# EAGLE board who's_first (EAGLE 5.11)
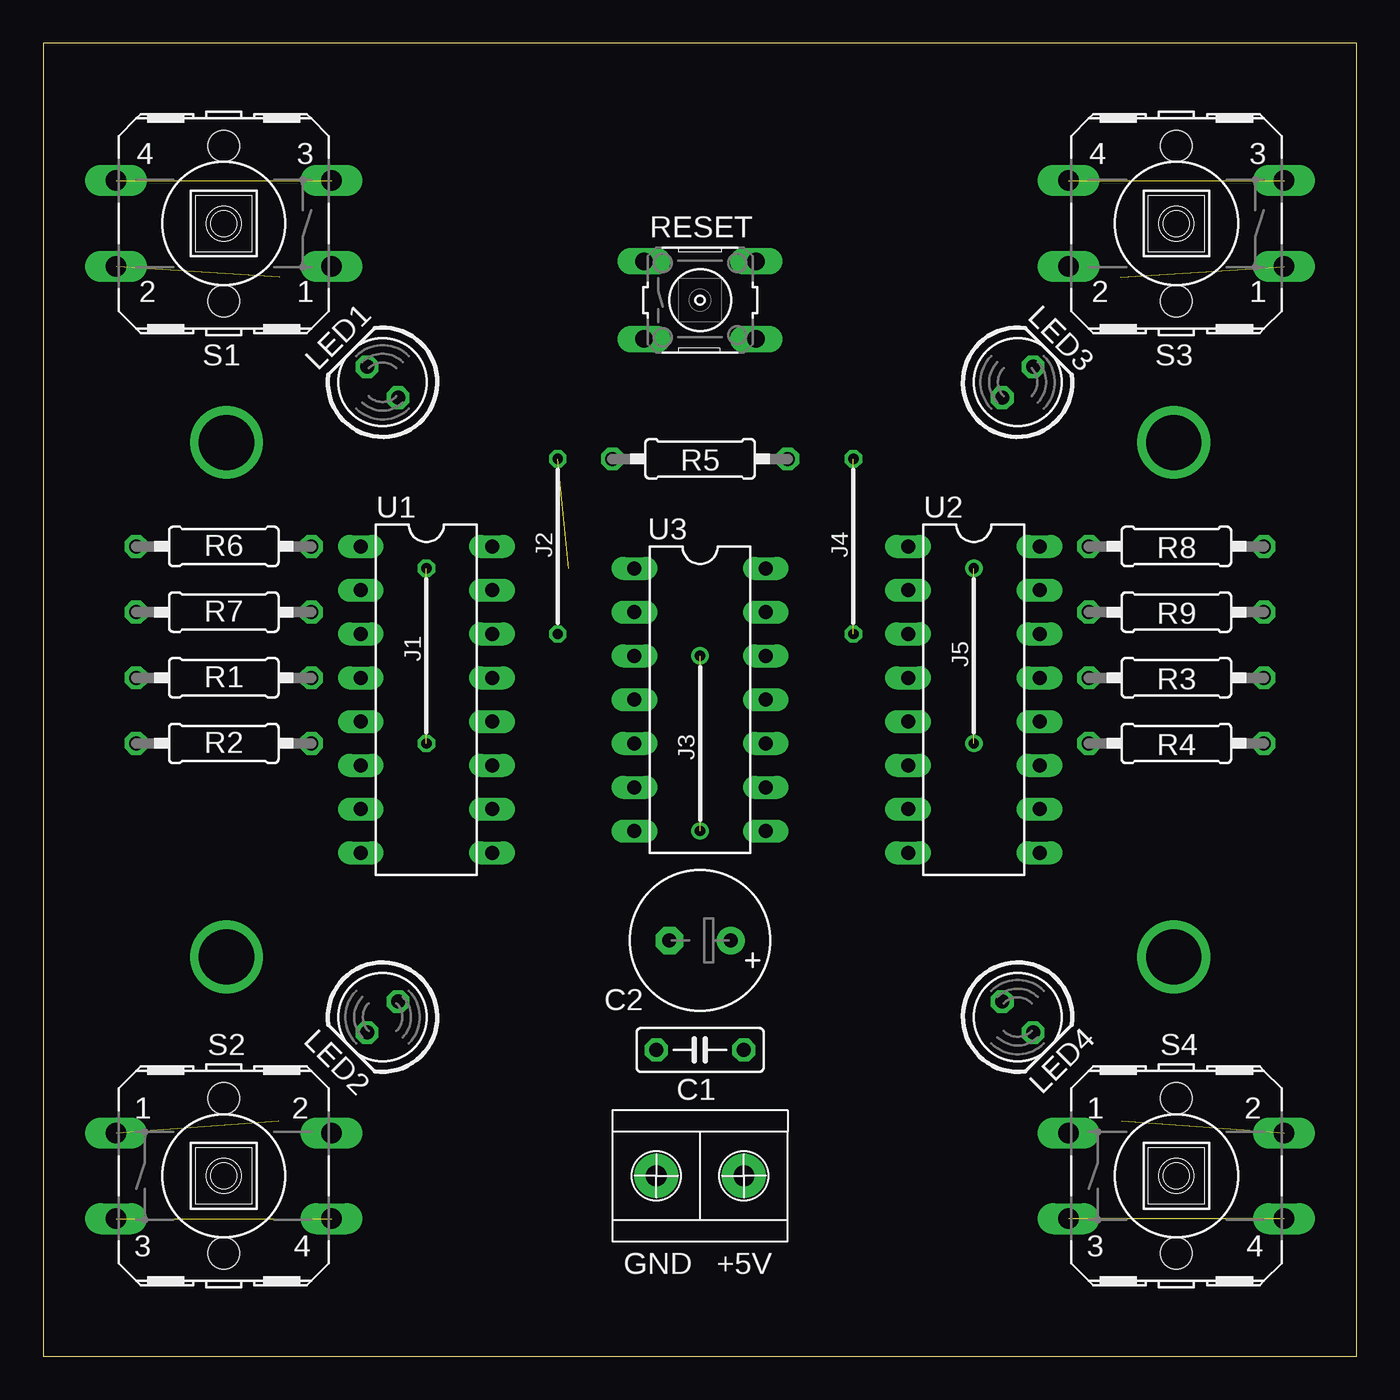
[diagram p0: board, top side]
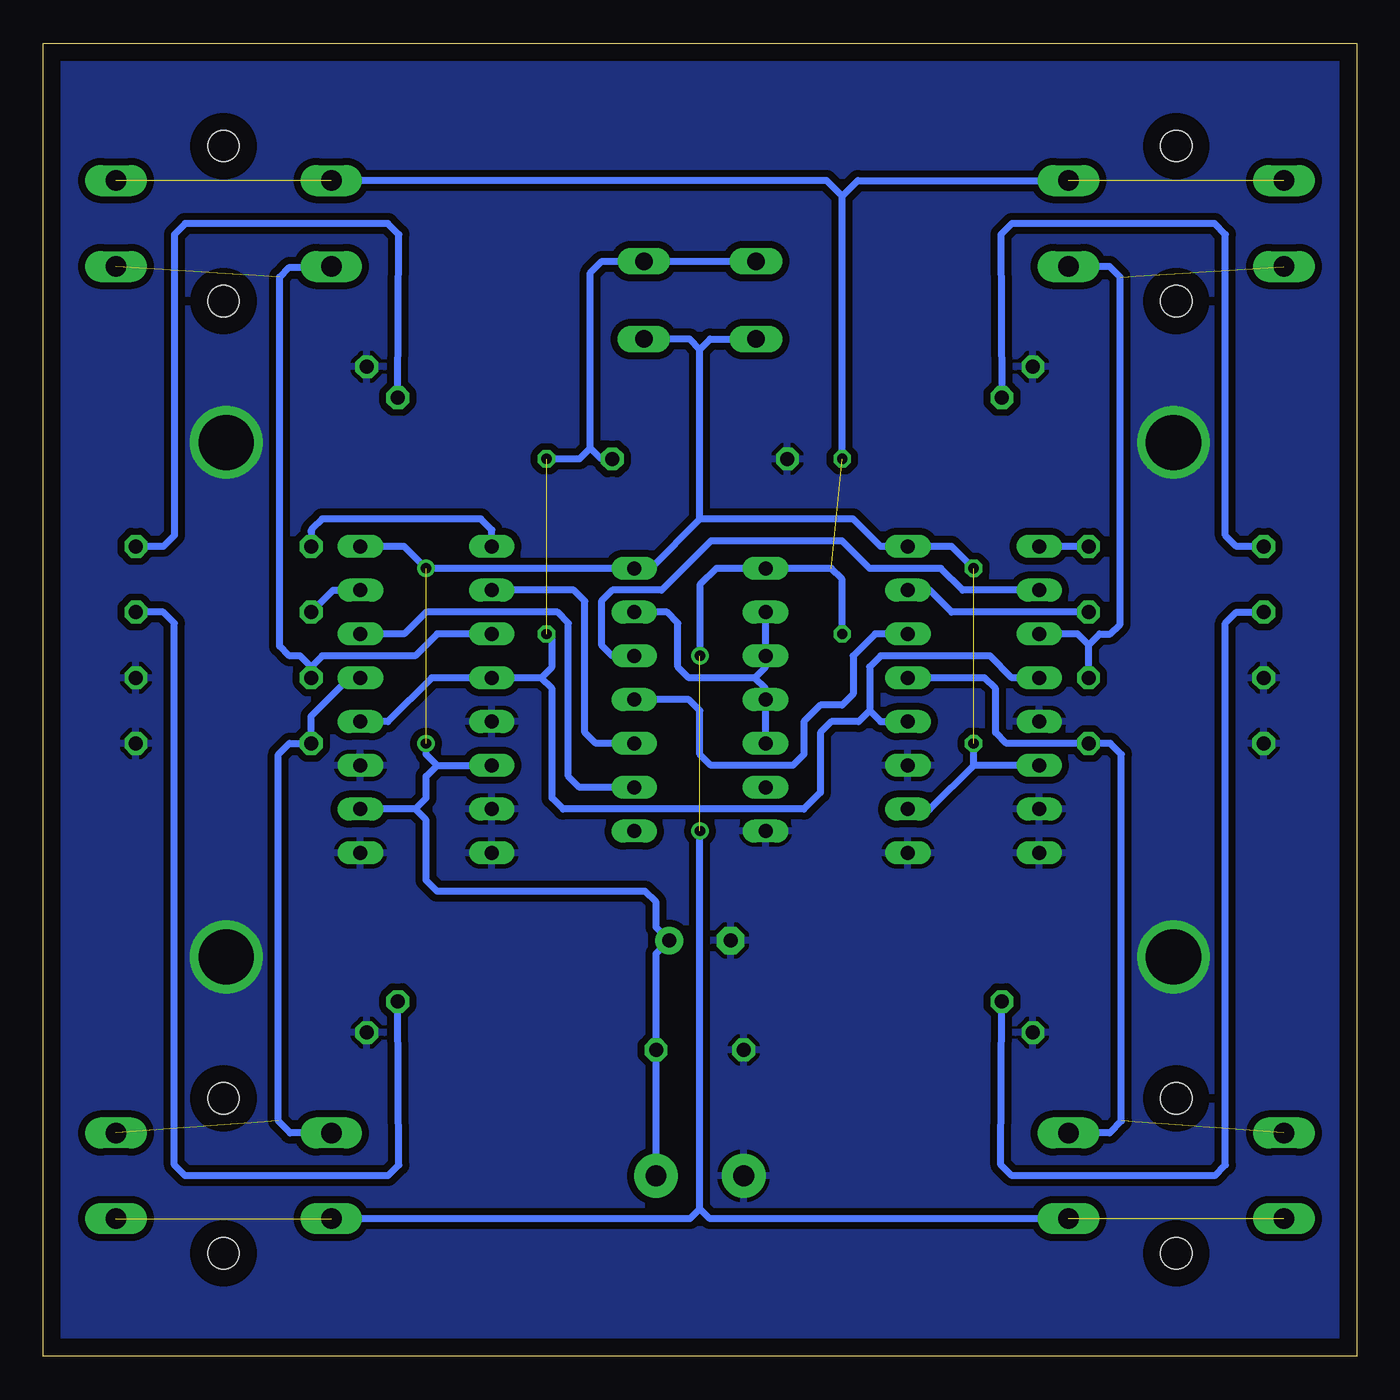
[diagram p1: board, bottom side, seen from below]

Size 76.19 x 76.19 mm. Coordinates in mm from the lower left corner, seen from the top.
Outline: 0,0 76.19,0 76.19,76.19 0,76.19 0,0
Copper layers (1*16): Top 0.035mm / dielectric 1.5mm / Bottom 0.035mm
Design rules "default": minimum track width 10mil, minimum drill 24mil, track to track 8mil, track to pad 8mil, pad to pad 8mil, via to via 8mil, smd to smd 8mil, copper to edge 40mil, drill to drill 8mil, minimum pad ring 10mil, minimum via ring 8mil, stop-mask expansion 4mil, vias tented up to drill 0mil, thermal gap 10mil

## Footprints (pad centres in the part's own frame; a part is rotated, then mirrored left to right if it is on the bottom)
C050-025X075 = drill 0.813 octagon: 1 -2.54,0; 2 2.54,0
E3,5-8 = drill 0.813 pad 1.6 round: + -1.778,0 | drill 0.813 pad 1.6 octagon: - 1.778,0
LED5MM = drill 0.813 octagon: A -1.27,0; K 1.27,0
0207/10 = drill 0.813 octagon: 1 -5.08,0; 2 5.08,0
B3F-10XX = drill 1.016 long: 1 -3.251,2.261; 2 3.251,2.261; 3 -3.251,-2.261; 4 3.251,-2.261
B3F-40XX = drill 1.194 long: 1 -6.248,2.489; 2 6.248,2.489; 3 -6.248,-2.489; 4 6.248,-2.489 | hole 1.803: 0,-4.496; 0,4.496
DIL16 = drill 0.813 long: 1 -8.89,-3.81; 2 -6.35,-3.81; 3 -3.81,-3.81; 4 -1.27,-3.81; 5 1.27,-3.81; 6 3.81,-3.81; 7 6.35,-3.81; 8 8.89,-3.81; 9 8.89,3.81; 10 6.35,3.81; 11 3.81,3.81; 12 1.27,3.81; 13 -1.27,3.81; 14 -3.81,3.81; 15 -6.35,3.81; 16 -8.89,3.81
DIL14 = drill 0.813 long: 1 -7.62,-3.81; 2 -5.08,-3.81; 3 -2.54,-3.81; 4 0,-3.81; 5 2.54,-3.81; 6 5.08,-3.81; 7 7.62,-3.81; 8 7.62,3.81; 9 5.08,3.81; 10 2.54,3.81; 11 0,3.81; 12 -2.54,3.81; 13 -5.08,3.81; 14 -7.62,3.81
ARK2 = drill 1.2 pad 2.54 round: 1 -2.54,0; 3 2.54,0 | drill 0.8 pad 2.54 round: 2 2.54,0

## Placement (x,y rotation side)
C1  100n  [C050-025X075]  38.1,17.78 180 top
C2  100u  [E3,5-8]  38.1,24.13 180 top
LED1  [LED5MM]  19.68,56.51 135 top
LED2  [LED5MM]  19.68,19.68 225 top
LED3  [LED5MM]  56.52,56.51 45 top
LED4  [LED5MM]  56.52,19.68 315 top
R1  100k  [0207/10]  10.48,39.37 180 top
R2  100k  [0207/10]  10.48,35.56 180 top
R3  100k  [0207/10]  65.72,39.37 0 top
R4  100k  [0207/10]  65.72,35.56 0 top
R5  100k  [0207/10]  38.1,52.07 0 top
R6  300  [0207/10]  10.48,46.99 180 top
R7  300  [0207/10]  10.48,43.18 180 top
R8  300  [0207/10]  65.72,46.99 0 top
R9  300  [0207/10]  65.72,43.18 0 top
RESET  [B3F-10XX]  38.1,61.28 0 top
S1  [B3F-40XX]  10.48,65.72 180 top
S2  [B3F-40XX]  10.48,10.48 0 top
S3  [B3F-40XX]  65.72,65.72 180 top
S4  [B3F-40XX]  65.72,10.48 0 top
U1  4027  [DIL16]  22.23,38.1 270 top
U2  4027  [DIL16]  53.97,38.1 270 top
U3  4012  [DIL14]  38.1,38.1 270 top
U$1  ARK2  [ARK2]  38.1,10.48 0 top

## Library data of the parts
C1 C2 R1-R9 = rcl
LED1-LED4 = led
RESET = switch-omron; MPN: B3F-1000; OC_FARNELL: 176432; OC_NEWARK: 36M3542
S1-S4 = switch-omron; MF: OMRON COMPONENTS USA; MPN: B3F-4000; OC_FARNELL: 176434; OC_NEWARK: 36K3105
U1-U3 = 40xx
U$1 = ark2

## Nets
GND: C1.2 C2.- LED1.K LED2.K LED3.K LED4.K R1.2 R2.2 R3.2 R4.2 R5.1 U1.5 U1.7 U1.8 U1.9 U1.11 U2.5 U2.7 U2.8 U2.9 U2.11 U3.7 U$1.1
N$1: R6.1 U1.1
N$2: R5.2 RESET.1 RESET.2 U1.4 U1.12 U2.4 U2.12
N$3: U1.2 U3.12
N$4: U1.14 U3.11
N$5: U2.2 U3.10
N$6: U2.14 U3.9
N$7: U3.2 U3.3 U3.4 U3.5 U3.13
N$8: C1.1 C2.+ RESET.3 RESET.4 U1.6 U1.10 U1.16 U2.6 U2.10 U2.16 U3.14 U$1.2
N$9: R7.1 U1.15
N$11: S1.3 S1.4 S2.3 S2.4 S3.3 S3.4 S4.3 S4.4 U3.1
N$12: R1.1 S1.1 S1.2 U1.3
N$13: R2.1 S2.1 S2.2 U1.13
N$14: R3.1 S3.1 S3.2 U2.3
N$15: R4.1 S4.1 S4.2 U2.13
N$16: R8.1 U2.1
N$17: R9.1 U2.15
N$18: LED1.A R6.2
N$19: LED2.A R7.2
N$20: LED3.A R8.2
N$21: LED4.A R9.2

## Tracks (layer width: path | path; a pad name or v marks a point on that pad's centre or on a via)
GND  (via drill 3.2)
  other vias: 10.64,53.02 65.56,53.02 10.64,23.18 65.56,23.18
  pour Bottom (isolate 0.406): -0.32,76.52 76.52,76.52 76.52,-0.32 -0.32,-0.32
N$1
  Bottom 0.406: R6.1 U1.1
N$2  (via drill 0.6)  (1 unrouted)
  Bottom 0.406: U2.12 56.2,36.83 53.66,39.37 U2.4 47.31,39.37 | 47.31,39.37 46.67,38.73 46.67,32.38 46.04,31.75 32.07,31.75 31.11,32.7 31.11,36.2 30.48,36.83 28.89,36.83 28.26,37.46 | U1.4 20,39.37 21.27,40.64 27.62,40.64 28.26,40 28.26,37.46 | RESET.1 RESET.2 43.78,63.54 44.45,62.87 44.45,52.7 | 44.45,52.7 43.82,52.07 R5.2 | 47.31,39.37 46.67,40 46.67,41.59 v46.99,41.91 | U1.12 27.62,36.83 28.26,37.46 | v46.99,52.07 45.08,52.07 44.45,52.7
N$3
  Bottom 0.406: U1.2 22.86,44.45 24.13,45.72 28.26,45.72 29.85,47.31 37.46,47.31 40.32,44.45 43.18,44.45 43.82,43.81 43.82,41.27 43.18,40.64 U3.12
N$4
  Bottom 0.406: U3.11 38.74,38.1 38.1,37.46 38.1,34.92 37.46,34.29 32.7,34.29 32.07,34.92 32.07,36.83 31.11,37.78 29.85,37.78 29.21,38.42 29.21,40.64 27.94,41.91 U1.14
N$5
  Bottom 0.406: U3.10 44.13,35.56 44.77,36.2 44.77,43.81 45.4,44.45 U2.2
N$6
  Bottom 0.406: U3.9 45.08,33.02 45.72,33.65 45.72,42.54 46.35,43.18 53.97,43.18 55.25,41.91 U2.14
N$7
  Bottom 0.406: U3.2 U3.3 34.29,40 34.93,39.37 | U3.5 U3.4 34.29,38.73 34.93,39.37 | U3.13 40,43.18 39.37,42.54 39.37,40 38.74,39.37 34.93,39.37
N$8  (via drill 0.6)  (2 unrouted)
  Bottom 0.406: U1.10 24.76,31.75 22.23,34.29 | U1.6 22.23,34.29 | v53.97,35.56 53.97,34.92 53.34,34.29 | 53.34,34.29 U2.6 | 54.61,31.75 U2.10 | 54.61,31.75 53.97,32.38 53.97,33.65 53.34,34.29 | U2.16 55.25,46.99 v53.97,45.72 U3.14 40.96,45.72 38.1,48.58 | 35.6,59.02 35.56,59.05 35.2,59.05 RESET.3 35.6,59.02 | 22.23,34.29 v22.23,35.56 | v22.23,45.72 23.5,46.99 U1.16 27.62,46.99 29.21,48.58 38.1,48.58 | 35.6,59.02 37.5,59.02 38.1,58.42 | RESET.4 38.7,59.02 38.1,58.42 | 54.61,31.75 53.97,31.11 53.97,27.62 53.34,26.99 41.28,26.99 40.64,26.35 40.64,24.89 C2.+ 40.64,23.37 C1.1 U$1.2 | 38.1,48.58 38.1,58.42
N$9
  Bottom 0.406: U1.15 24.76,44.45 23.5,43.18 R7.1
N$11  (via drill 0.6)  (6 unrouted)
  Bottom 0.406: v38.1,40.64 38.1,44.77 37.15,45.72 U3.1 30.48,45.72 29.85,45.08 v29.85,41.91 | S4.3 38.68,7.99 38.1,8.57 | 38.1,8.57 v38.1,30.48 | S2.4 37.52,7.99 38.1,8.57 | S1.3 28.94,68.21 29.85,67.31 | S3.4 30.75,68.21 29.85,67.31 | v29.85,52.07 29.85,67.31
N$12  (1 unrouted)
  Bottom 0.406: R1.1 15.56,41.27 | 15.56,41.27 16.19,41.91 U1.3 | S1.1 14.34,63.23 13.73,62.62 13.73,42.47 14.29,41.91 14.92,41.91 15.56,41.27
N$13  (1 unrouted)
  Bottom 0.406: U1.13 21.59,39.37 20.96,38.73 20.96,36.2 20.32,35.56 R2.1 14.29,35.56 13.65,34.92 13.65,13.65 14.34,12.97 S2.2
N$14  (1 unrouted)
  Bottom 0.406: S3.2 59.52,63.18 61.91,63.18 62.47,62.62 62.47,41.2 61.91,40.64 61.28,40.64 60.64,40 | U2.3 53.34,41.91 54.61,40.64 60.01,40.64 60.64,40 | 60.64,40 R3.1
N$15  (1 unrouted)
  Bottom 0.406: U2.13 58.42,39.37 60.64,37.15 R4.1 61.91,35.56 62.55,34.92 62.55,13.65 61.86,12.97 S4.1
N$16
  Bottom 0.406: U2.1 50.17,47.94 50.8,48.58 60.01,48.58 60.57,48.02 arc-45 60.64,47.84 R8.1
N$17
  Bottom 0.406: U2.15 59.37,44.45 R9.1
N$18
  Bottom 0.406: R6.2 6.98,46.99 7.62,47.62 7.62,65.09 8.25,65.72 20,65.72 20.64,65.09 LED1.A
N$19
  Bottom 0.406: R7.2 6.98,43.18 7.62,42.54 7.62,11.11 8.25,10.48 20,10.48 20.64,11.11 LED2.A
N$20
  Bottom 0.406: R8.2 69.21,46.99 68.58,47.62 68.58,65.09 67.95,65.72 56.2,65.72 55.56,65.09 LED3.A
N$21
  Bottom 0.406: LED4.A 55.56,11.11 56.2,10.48 67.95,10.48 68.58,11.11 68.58,42.54 69.21,43.18 R9.2

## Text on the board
tPlace: J2 | J4 | J1 | J5 | J3 | GND | +5V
